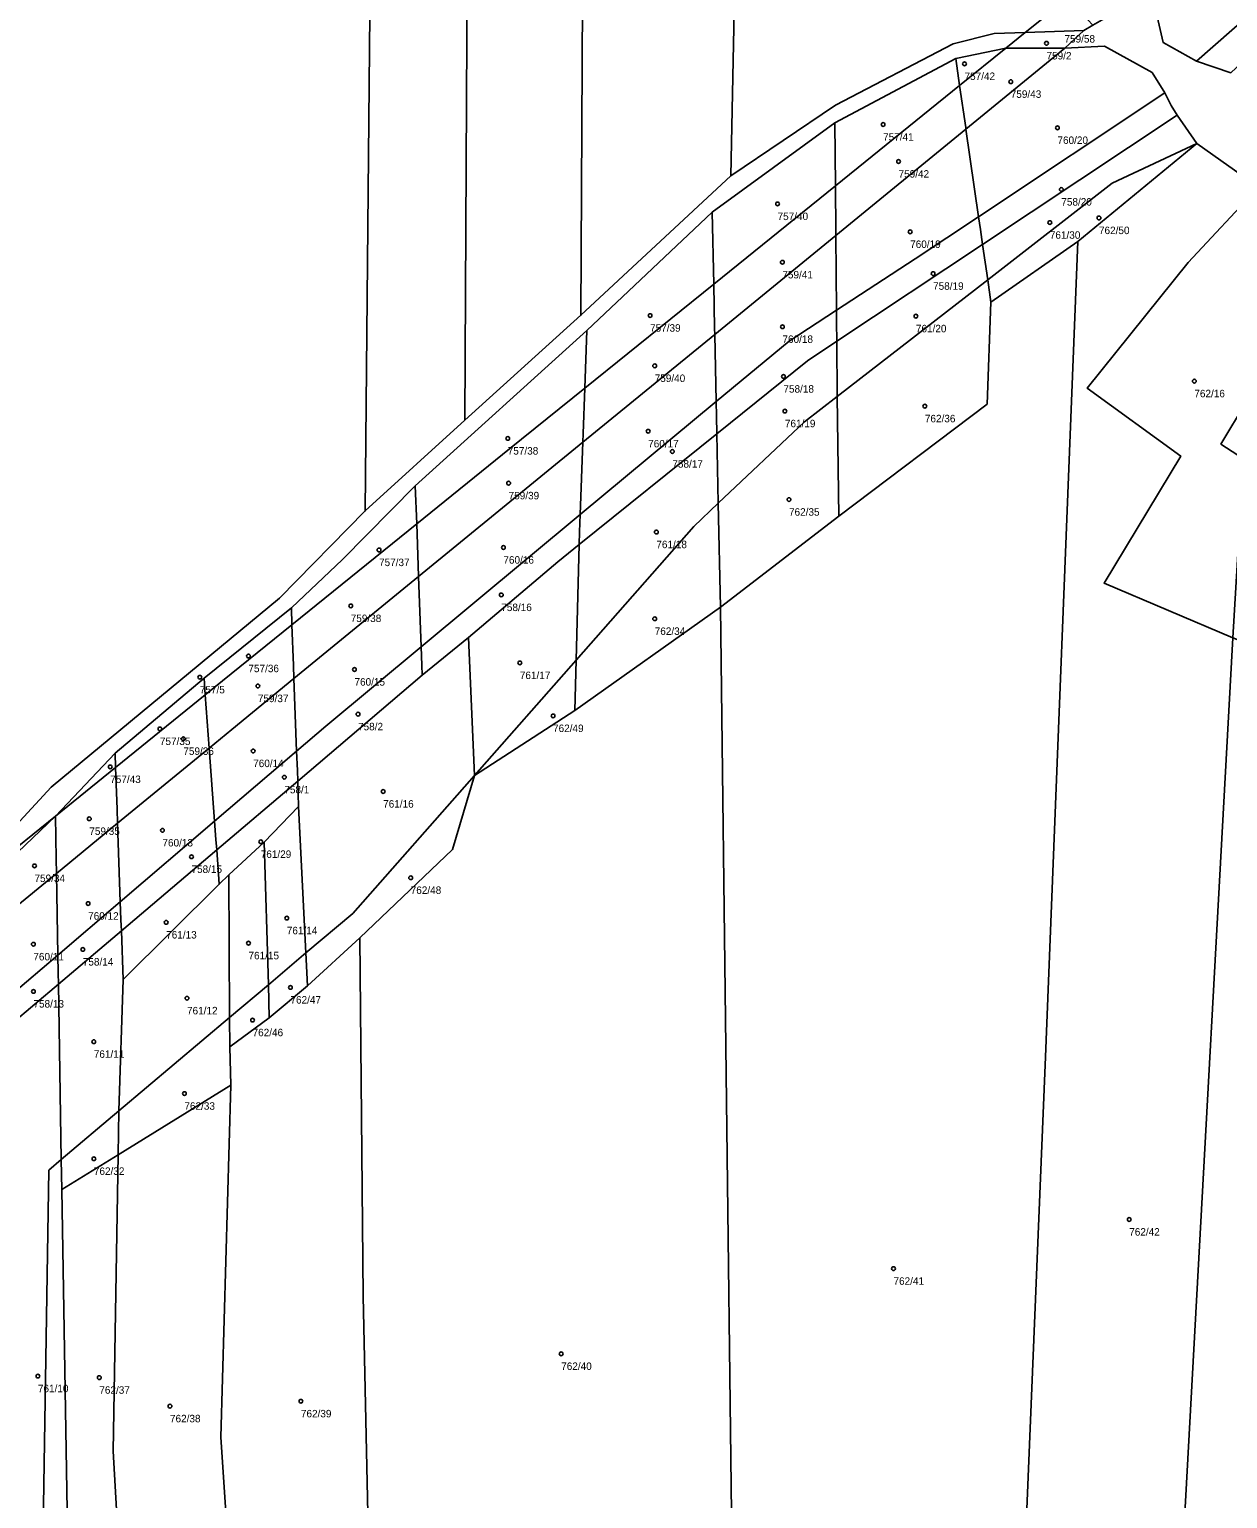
# Model space of a CAD drawing. Extents: x -587171 to -555306, y -1167727 to -1074732.
# Drawn here: x -586038.1 to -585877.6, y -1165235.6 to -1165038.9 of the extents above; entities that cross this region are included whole.
import ezdxf

# ---------------------------------------------------------------- set-up
doc = ezdxf.new("R2010")
doc.units = 0
doc.layers.add('Definiční body', color=7, linetype='Continuous')
doc.layers.add('Polygon parcely', color=7, linetype='Continuous')

msp = doc.modelspace()

# ---------------------------------------------------------------- linework, layer by layer
at = {"layer": 'Definiční body'}
for centre in [(-585901.88, -1165040.78), (-585912.86, -1165043.53), (-585906.67, -1165045.92), (-585923.76, -1165051.65), (-585900.42, -1165052.09), (-585921.69, -1165056.6), (-585899.9, -1165060.34), (-585937.89, -1165062.28), (-585901.44, -1165064.78), (-585894.86, -1165064.16), (-585920.14, -1165066.01), (-585937.25, -1165070.09), (-585917.07, -1165071.61), (-585954.96, -1165077.22), (-585937.24, -1165078.72), (-585919.37, -1165077.3), (-585954.34, -1165083.95), (-585937.11, -1165085.38), (-585882.09, -1165086), (-585936.91, -1165090.01), (-585918.17, -1165089.35), (-585955.22, -1165092.71), (-585974.02, -1165093.67), (-585951.98, -1165095.42), (-585973.9, -1165099.66), (-585936.36, -1165101.85), (-585954.12, -1165106.2), (-585991.25, -1165108.6), (-585974.6, -1165108.27), (-585974.88, -1165114.62), (-585995.04, -1165116.09), (-585954.34, -1165117.81), (-586008.74, -1165122.8), (-585972.4, -1165123.72), (-586015.24, -1165125.64), (-585994.54, -1165124.6), (-586007.47, -1165126.81), (-585994.06, -1165130.58), (-585967.95, -1165130.81), (-586020.59, -1165132.55), (-586017.45, -1165133.87), (-586008.1, -1165135.51), (-586027.24, -1165137.64), (-586003.93, -1165139.02), (-585990.7, -1165140.93), (-586030.04, -1165144.58), (-586020.25, -1165146.13), (-586007.09, -1165147.66), (-586016.36, -1165149.67), (-586037.38, -1165150.89), (-585987.01, -1165152.48), (-586030.2, -1165155.93), (-586003.6, -1165157.88), (-586019.75, -1165158.45), (-586037.53, -1165161.38), (-586008.73, -1165161.23), (-586030.91, -1165162.07), (-586037.52, -1165167.69), (-586003.11, -1165167.16), (-586016.96, -1165168.6), (-586008.18, -1165171.53), (-586029.44, -1165174.42), (-586017.31, -1165181.37), (-586029.43, -1165190.09), (-585890.81, -1165198.22), (-585922.37, -1165204.8), (-585966.86, -1165216.2), (-586036.92, -1165219.18), (-586028.7, -1165219.39), (-586001.71, -1165222.55), (-586019.24, -1165223.21)]:
    msp.add_circle(centre, 0.25, dxfattribs=at)
at = {"layer": 'Polygon parcely'}
for points in [[(-585991.62, -1164946.53), (-586054.54, -1164903.67), (-586053.49, -1165012.75), (-586050.93, -1165157.45), (-586035.13, -1165140.36), (-586004.57, -1165115.05), (-585993.09, -1165103.37)], [(-585979.06, -1164954.55), (-585991.62, -1164946.53), (-585993.09, -1165103.37), (-585979.78, -1165091.21)], [(-585963.64, -1164967.62), (-585979.06, -1164954.55), (-585979.78, -1165091.21), (-585964.22, -1165077.17)], [(-585944.13, -1165058.5), (-585942.7, -1164987.94), (-585963.64, -1164967.62), (-585964.22, -1165077.17)], [(-585899.03, -1165034.73), (-585921.41, -1165010.35), (-585942.7, -1164987.94), (-585944.13, -1165058.5), (-585930.15, -1165049.07), (-585914.37, -1165040.86), (-585908.87, -1165039.46), (-585904.72, -1165039.32)], [(-585847.61, -1165013.14), (-585847.1, -1165001), (-585865.01, -1165015.12), (-585887.83, -1165033.85), (-585886.26, -1165040.68), (-585881.8, -1165043.17)], [(-585847.78, -1165017.2), (-585847.61, -1165013.14), (-585881.8, -1165043.17), (-585877.21, -1165044.73)], [(-585896.88, -1165039.06), (-585895.69, -1165038.37), (-585899.03, -1165034.73), (-585904.72, -1165039.32)], [(-585930.21, -1165051.41), (-585914.04, -1165042.8), (-585907.32, -1165041.42), (-585904.72, -1165039.32), (-585908.87, -1165039.46), (-585914.37, -1165040.86), (-585930.15, -1165049.07), (-585944.13, -1165058.5), (-585964.22, -1165077.17), (-585979.78, -1165091.21), (-585993.09, -1165103.37), (-586004.57, -1165115.05), (-586035.13, -1165140.36), (-586050.93, -1165157.45), (-586034.57, -1165144.23), (-586026.6, -1165135.8), (-586014.68, -1165125.74), (-586002.99, -1165116.35), (-585996.14, -1165109.88), (-585986.39, -1165100), (-585963.41, -1165079.23), (-585946.64, -1165063.37)], [(-585899.43, -1165041.45), (-585896.88, -1165039.06), (-585904.72, -1165039.32), (-585907.32, -1165041.42)], [(-585907.32, -1165041.42), (-585914.04, -1165042.8), (-585913.52, -1165046.42)], [(-585899.43, -1165041.45), (-585907.32, -1165041.42), (-585913.52, -1165046.42), (-585912.7, -1165052.07), (-585912.67, -1165052.27)], [(-585886.03, -1165047.41), (-585887.74, -1165044.68), (-585894.14, -1165041.18), (-585899.43, -1165041.45), (-585912.67, -1165052.27), (-585910.98, -1165063.99)], [(-585914.04, -1165042.8), (-585930.21, -1165051.41), (-585930.14, -1165059.84), (-585913.52, -1165046.42)], [(-585912.67, -1165052.27), (-585912.7, -1165052.07), (-585913.52, -1165046.42), (-585930.14, -1165059.84), (-585930.09, -1165065.97), (-585930.09, -1165066.51)], [(-585910.98, -1165063.99), (-585910.74, -1165065.68), (-585910.45, -1165067.69), (-585884.41, -1165050.39), (-585885.18, -1165049.11), (-585886.03, -1165047.41)], [(-585930.14, -1165059.84), (-585930.21, -1165051.41), (-585946.64, -1165063.37), (-585946.44, -1165073.01)], [(-585881.75, -1165054.17), (-585884.41, -1165050.39), (-585910.45, -1165067.69), (-585909.76, -1165072.43), (-585893.09, -1165059.49)], [(-585912.67, -1165052.27), (-585930.09, -1165066.51), (-585930, -1165076.49), (-585919.48, -1165069.64), (-585910.98, -1165063.99)], [(-585881.75, -1165054.17), (-585893.09, -1165059.49), (-585909.76, -1165072.43), (-585909.33, -1165075.43), (-585897.71, -1165067.32)], [(-585886.63, -1165297.03), (-585876.95, -1165120.35), (-585894.18, -1165113.04), (-585883.91, -1165096.03), (-585896.44, -1165086.92), (-585882.93, -1165070.13), (-585873.52, -1165060.03), (-585881.75, -1165054.17), (-585897.71, -1165067.32), (-585902.01, -1165176.43), (-585907.05, -1165298.6), (-585895.08, -1165296.86)], [(-585930.09, -1165066.51), (-585930.09, -1165065.97), (-585930.14, -1165059.84), (-585946.44, -1165073.01), (-585946.32, -1165078.95), (-585946.3, -1165079.76)], [(-585875.11, -1165088.73), (-585873.52, -1165060.03), (-585882.93, -1165070.13), (-585896.44, -1165086.92), (-585883.91, -1165096.03), (-585894.18, -1165113.04), (-585876.95, -1165120.35), (-585875.49, -1165096.38), (-585878.54, -1165094.43)], [(-585946.44, -1165073.01), (-585946.64, -1165063.37), (-585963.41, -1165079.23), (-585963.69, -1165086.94)], [(-585930, -1165076.49), (-585929.98, -1165078.15), (-585929.96, -1165080.66), (-585910.45, -1165067.69), (-585910.74, -1165065.68), (-585910.98, -1165063.99), (-585919.48, -1165069.64)], [(-585930.09, -1165066.51), (-585946.3, -1165079.76), (-585946.11, -1165088.74), (-585936.36, -1165080.63), (-585930, -1165076.49)], [(-585907.05, -1165298.6), (-585902.01, -1165176.43), (-585897.71, -1165067.32), (-585909.33, -1165075.43), (-585909.82, -1165089.08), (-585929.67, -1165104.07), (-585945.54, -1165116.26), (-585943.24, -1165303.67), (-585913.05, -1165299.45)], [(-585909.76, -1165072.43), (-585910.45, -1165067.69), (-585929.96, -1165080.66), (-585929.89, -1165088.04)], [(-585849.05, -1165078.74), (-585853.58, -1165075.82), (-585863.51, -1165069.4), (-585875.11, -1165088.73), (-585878.54, -1165094.43), (-585875.49, -1165096.38), (-585863.91, -1165103.41), (-585861.07, -1165098.7), (-585854.23, -1165087.34)], [(-585946.44, -1165073.01), (-585963.69, -1165086.94), (-585963.91, -1165093.02), (-585963.95, -1165094.19), (-585946.3, -1165079.76), (-585946.32, -1165078.95)], [(-585909.76, -1165072.43), (-585929.89, -1165088.04), (-585929.67, -1165104.07), (-585909.82, -1165089.08), (-585909.33, -1165075.43)], [(-585930, -1165076.49), (-585936.36, -1165080.63), (-585946.11, -1165088.74), (-585946.07, -1165090.7), (-585946.02, -1165093.04), (-585933.9, -1165083.28), (-585929.96, -1165080.66), (-585929.98, -1165078.15)], [(-585963.69, -1165086.94), (-585963.41, -1165079.23), (-585986.39, -1165100), (-585986.2, -1165105.12), (-585973.78, -1165095.08)], [(-585946.3, -1165079.76), (-585963.95, -1165094.19), (-585964.31, -1165103.86), (-585946.11, -1165088.74)], [(-585929.96, -1165080.66), (-585933.9, -1165083.28), (-585946.02, -1165093.04), (-585945.83, -1165102.34), (-585934.27, -1165091.44), (-585929.89, -1165088.04)], [(-585963.69, -1165086.94), (-585973.78, -1165095.08), (-585986.2, -1165105.12), (-585986, -1165110.68), (-585985.95, -1165112.17), (-585963.95, -1165094.19), (-585963.91, -1165093.02)], [(-585964.31, -1165103.86), (-585964.4, -1165106.19), (-585964.45, -1165107.88), (-585946.02, -1165093.04), (-585946.07, -1165090.7), (-585946.11, -1165088.74)], [(-585929.67, -1165104.07), (-585929.89, -1165088.04), (-585934.27, -1165091.44), (-585945.83, -1165102.34), (-585945.54, -1165116.26)], [(-585963.95, -1165094.19), (-585985.95, -1165112.17), (-585985.6, -1165121.55), (-585964.31, -1165103.86)], [(-585949.12, -1165105.45), (-585945.83, -1165102.34), (-585946.02, -1165093.04), (-585964.45, -1165107.88), (-585964.87, -1165123.33)], [(-585986.2, -1165105.12), (-585986.39, -1165100), (-585996.14, -1165109.88), (-586002.99, -1165116.35), (-586002.91, -1165118.63)], [(-585965.05, -1165130.07), (-585945.54, -1165116.26), (-585945.83, -1165102.34), (-585949.12, -1165105.45), (-585964.87, -1165123.33)], [(-585979.27, -1165120.3), (-585967.31, -1165110.19), (-585964.45, -1165107.88), (-585964.4, -1165106.19), (-585964.31, -1165103.86), (-585985.6, -1165121.55), (-585985.51, -1165124.04), (-585985.46, -1165125.37)], [(-585985.95, -1165112.17), (-585986, -1165110.68), (-585986.2, -1165105.12), (-586002.91, -1165118.63), (-586002.71, -1165124.05), (-586002.64, -1165125.82)], [(-585964.87, -1165123.33), (-585964.45, -1165107.88), (-585967.31, -1165110.19), (-585979.27, -1165120.3), (-585978.48, -1165138.78)], [(-585985.6, -1165121.55), (-585985.95, -1165112.17), (-586002.64, -1165125.82), (-586002.28, -1165135.51), (-585998.39, -1165132.18)], [(-585978.48, -1165138.78), (-585981.42, -1165148.71), (-585993.8, -1165160.54), (-585993.37, -1165208.49), (-585991.77, -1165283.22), (-585982.19, -1165290.86), (-585976.85, -1165294.27), (-585969.25, -1165299.02), (-585955.07, -1165303.18), (-585943.24, -1165303.67), (-585945.54, -1165116.26), (-585965.05, -1165130.07)], [(-586002.91, -1165118.63), (-586002.99, -1165116.35), (-586014.68, -1165125.74), (-586014.51, -1165128.01)], [(-586002.91, -1165118.63), (-586014.51, -1165128.01), (-586014.12, -1165133.35), (-586013.99, -1165135.11), (-586010.96, -1165132.62), (-586002.64, -1165125.82), (-586002.71, -1165124.05)], [(-586002.28, -1165135.51), (-586002.18, -1165138.14), (-586002.13, -1165139.53), (-585985.46, -1165125.37), (-585985.51, -1165124.04), (-585985.6, -1165121.55), (-585998.39, -1165132.18)], [(-585979.27, -1165120.3), (-585985.46, -1165125.37), (-586002.13, -1165139.53), (-586002.01, -1165142.92), (-586001.03, -1165162.54), (-585994.76, -1165157.25), (-585978.48, -1165138.78)], [(-585864.03, -1165297.55), (-585856.06, -1165132.46), (-585873.96, -1165121.53), (-585876.95, -1165120.35), (-585886.63, -1165297.03), (-585872.33, -1165297.33)], [(-585964.87, -1165123.33), (-585978.48, -1165138.78), (-585965.05, -1165130.07)], [(-586014.51, -1165128.01), (-586014.68, -1165125.74), (-586026.6, -1165135.8), (-586026.53, -1165137.73)], [(-586002.64, -1165125.82), (-586010.96, -1165132.62), (-586013.99, -1165135.11), (-586013.26, -1165144.9), (-586002.28, -1165135.51)], [(-586013.99, -1165135.11), (-586014.12, -1165133.35), (-586014.51, -1165128.01), (-586026.53, -1165137.73), (-586026.33, -1165143.31), (-586026.26, -1165145.19)], [(-586026.53, -1165137.73), (-586026.6, -1165135.8), (-586034.57, -1165144.23)], [(-586013.26, -1165144.9), (-586013.99, -1165135.11), (-586026.26, -1165145.19), (-586025.89, -1165155.69)], [(-586013.26, -1165144.9), (-586013.08, -1165147.35), (-586012.98, -1165148.74), (-586002.13, -1165139.53), (-586002.18, -1165138.14), (-586002.28, -1165135.51)], [(-586026.26, -1165145.19), (-586026.33, -1165143.31), (-586026.53, -1165137.73), (-586034.57, -1165144.23), (-586034.47, -1165149.95), (-586034.44, -1165151.91)], [(-586002.13, -1165139.53), (-586012.98, -1165148.74), (-586012.64, -1165153.34), (-586011.38, -1165152.1), (-586006.62, -1165147.72), (-586002.01, -1165142.92)], [(-585978.48, -1165138.78), (-585994.76, -1165157.25), (-586001.03, -1165162.54), (-586000.81, -1165166.93), (-585993.8, -1165160.54), (-585981.42, -1165148.71)], [(-586002.01, -1165142.92), (-586006.62, -1165147.72), (-586006.07, -1165166.8), (-586001.03, -1165162.54)], [(-586086.14, -1165186.99), (-586076.2, -1165182.3), (-586066.92, -1165176.4), (-586065.37, -1165175.41), (-586058.02, -1165169.9), (-586055.37, -1165166.98), (-586048.79, -1165159.73), (-586040.62, -1165150.04), (-586034.57, -1165144.23), (-586050.93, -1165157.45), (-586058.53, -1165167.45), (-586065.33, -1165173.02), (-586080.4, -1165181.26), (-586087.75, -1165187.23)], [(-586034.44, -1165151.91), (-586034.47, -1165149.95), (-586034.57, -1165144.23), (-586040.62, -1165150.04), (-586040.6, -1165154.94), (-586040.59, -1165156.96)], [(-586025.89, -1165155.69), (-586026.26, -1165145.19), (-586034.44, -1165151.91), (-586034.25, -1165162.84)], [(-586025.89, -1165155.69), (-586025.8, -1165158.1), (-586025.75, -1165159.59), (-586012.98, -1165148.74), (-586013.08, -1165147.35), (-586013.26, -1165144.9)], [(-586006.07, -1165166.8), (-586006.62, -1165147.72), (-586011.38, -1165152.1), (-586011.25, -1165171.17)], [(-586012.64, -1165153.34), (-586012.98, -1165148.74), (-586025.75, -1165159.59), (-586025.51, -1165166.11)], [(-586034.25, -1165162.84), (-586034.44, -1165151.91), (-586040.59, -1165156.96), (-586040.54, -1165168.21)], [(-586011.38, -1165152.1), (-586012.64, -1165153.34), (-586025.51, -1165166.11), (-586026.07, -1165183.69), (-586011.25, -1165171.17)], [(-586034.18, -1165166.72), (-586025.75, -1165159.59), (-586025.8, -1165158.1), (-586025.89, -1165155.69), (-586034.25, -1165162.84), (-586034.21, -1165165.21)], [(-586026.07, -1165183.69), (-586025.51, -1165166.11), (-586025.75, -1165159.59), (-586034.18, -1165166.72), (-586033.79, -1165190.21)], [(-585993.37, -1165208.49), (-585993.8, -1165160.54), (-586000.81, -1165166.93), (-586005.94, -1165171.23), (-586011.22, -1165175.11), (-586011.11, -1165180.26), (-586012.43, -1165227.35), (-586009.68, -1165268.95), (-585994.93, -1165280.7), (-585991.77, -1165283.22)], [(-586040.52, -1165172.08), (-586034.18, -1165166.72), (-586034.21, -1165165.21), (-586034.25, -1165162.84), (-586040.54, -1165168.21), (-586040.53, -1165170.55)], [(-586000.81, -1165166.93), (-586001.03, -1165162.54), (-586006.07, -1165166.8), (-586005.94, -1165171.23)], [(-586033.79, -1165190.21), (-586034.18, -1165166.72), (-586040.52, -1165172.08), (-586040.27, -1165234.18), (-586039.3, -1165290.74), (-586031.18, -1165294.22), (-586032.77, -1165250.56), (-586036.34, -1165247.72), (-586035.46, -1165191.62)], [(-586006.07, -1165166.8), (-586011.25, -1165171.17), (-586011.22, -1165175.11), (-586005.94, -1165171.23)], [(-586011.11, -1165180.26), (-586011.22, -1165175.11), (-586011.25, -1165171.17), (-586026.07, -1165183.69), (-586026.17, -1165189.55)], [(-586012.43, -1165227.35), (-586011.11, -1165180.26), (-586026.17, -1165189.55), (-586026.83, -1165229.24), (-586025.28, -1165256.53), (-586009.68, -1165268.95)], [(-586033.72, -1165194.21), (-586026.17, -1165189.55), (-586026.07, -1165183.69), (-586033.79, -1165190.21)], [(-586036.34, -1165247.72), (-586032.77, -1165250.56), (-586033.72, -1165194.21), (-586033.79, -1165190.21), (-586035.46, -1165191.62)], [(-586025.28, -1165256.53), (-586026.83, -1165229.24), (-586026.17, -1165189.55), (-586033.72, -1165194.21), (-586032.77, -1165250.56)]]:
    msp.add_lwpolyline(points, close=True, dxfattribs=at)
msp.add_lwpolyline([(-585877.21, -1165044.73), (-585881.8, -1165043.17), (-585886.26, -1165040.68), (-585887.83, -1165033.85), (-585892.23, -1165036.38), (-585895.69, -1165038.37), (-585896.88, -1165039.06), (-585899.43, -1165041.45), (-585894.14, -1165041.18), (-585887.74, -1165044.68), (-585886.03, -1165047.41), (-585885.18, -1165049.11), (-585884.41, -1165050.39), (-585881.75, -1165054.17), (-585873.52, -1165060.03)], dxfattribs=at)

# ---------------------------------------------------------------- texts
at = {"layer": 'Definiční body'}
for s, p in [('759/58', (-585899.48, -1165040.68)), ('759/2', (-585901.88, -1165042.94)), ('757/42', (-585912.86, -1165045.69)), ('759/43', (-585906.67, -1165048.08)), ('757/41', (-585923.76, -1165053.81)), ('760/20', (-585900.42, -1165054.25)), ('759/42', (-585921.69, -1165058.76)), ('758/20', (-585899.9, -1165062.5)), ('757/40', (-585937.89, -1165064.44)), ('760/19', (-585920.14, -1165068.17)), ('761/30', (-585901.44, -1165066.94)), ('762/50', (-585894.86, -1165066.32)), ('759/41', (-585937.25, -1165072.25)), ('758/19', (-585917.07, -1165073.77)), ('757/39', (-585954.96, -1165079.38)), ('761/20', (-585919.37, -1165079.46)), ('760/18', (-585937.24, -1165080.88)), ('759/40', (-585954.34, -1165086.11)), ('758/18', (-585937.11, -1165087.54)), ('762/16', (-585882.09, -1165088.16)), ('762/36', (-585918.17, -1165091.51)), ('761/19', (-585936.91, -1165092.17)), ('760/17', (-585955.22, -1165094.87)), ('757/38', (-585974.02, -1165095.83)), ('758/17', (-585951.98, -1165097.58)), ('759/39', (-585973.9, -1165101.82)), ('762/35', (-585936.36, -1165104.01)), ('761/18', (-585954.12, -1165108.36)), ('757/37', (-585991.25, -1165110.76)), ('760/16', (-585974.6, -1165110.43)), ('758/16', (-585974.88, -1165116.78)), ('759/38', (-585995.04, -1165118.25)), ('762/34', (-585954.34, -1165119.97)), ('757/36', (-586008.74, -1165124.96)), ('760/15', (-585994.54, -1165126.76)), ('761/17', (-585972.4, -1165125.88)), ('757/5', (-586015.24, -1165127.8)), ('759/37', (-586007.47, -1165128.97)), ('758/2', (-585994.06, -1165132.74)), ('762/49', (-585967.95, -1165132.97)), ('757/35', (-586020.59, -1165134.71)), ('759/36', (-586017.45, -1165136.03)), ('760/14', (-586008.1, -1165137.67)), ('757/43', (-586027.24, -1165139.8)), ('758/1', (-586003.93, -1165141.18)), ('761/16', (-585990.7, -1165143.09)), ('759/35', (-586030.04, -1165146.74)), ('760/13', (-586020.25, -1165148.29)), ('761/29', (-586007.09, -1165149.82)), ('758/15', (-586016.36, -1165151.83)), ('759/34', (-586037.38, -1165153.05)), ('762/48', (-585987.01, -1165154.64)), ('760/12', (-586030.2, -1165158.09)), ('761/13', (-586019.75, -1165160.61)), ('761/14', (-586003.6, -1165160.04)), ('760/11', (-586037.53, -1165163.54)), ('758/14', (-586030.91, -1165164.23)), ('761/15', (-586008.73, -1165163.39)), ('758/13', (-586037.52, -1165169.85)), ('762/47', (-586003.11, -1165169.32)), ('761/12', (-586016.96, -1165170.76)), ('762/46', (-586008.18, -1165173.69)), ('761/11', (-586029.44, -1165176.58)), ('762/33', (-586017.31, -1165183.53)), ('762/32', (-586029.43, -1165192.25)), ('762/42', (-585890.81, -1165200.38)), ('762/41', (-585922.37, -1165206.96)), ('762/40', (-585966.86, -1165218.36)), ('761/10', (-586036.92, -1165221.34)), ('762/37', (-586028.7, -1165221.55)), ('762/38', (-586019.24, -1165225.37)), ('762/39', (-586001.71, -1165224.71))]:
    msp.add_text(s, height=1, dxfattribs=at).set_placement(p)

doc.saveas('drawing.dxf')
